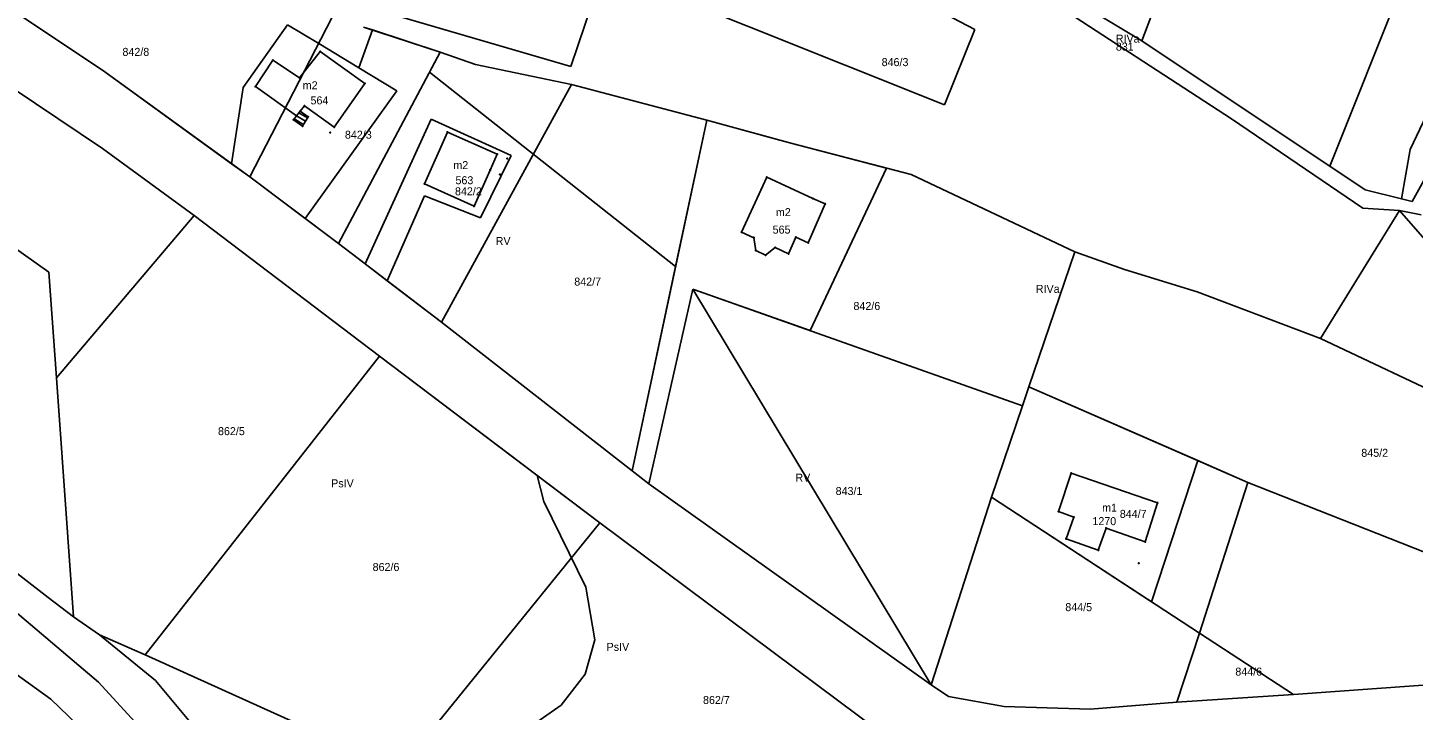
# Model space of a CAD drawing. Extents: x 7498273 to 7499989, y 5499795 to 5500810.
# Drawn here: x 7499281.1 to 7499540.8, y 5500223.1 to 5500351 of the extents above; entities that cross this region are included whole.
import ezdxf

# ---------------------------------------------------------------- set-up
doc = ezdxf.new("R2010")
doc.units = 0
for name, color, linetype in [('209-oznaczenie konturu klasyfikacyjnego', 7, 'Continuous'), ('211-numer działki ewidencyjnej', 7, 'Continuous'), ('217-kontur klasyfikacyjny', 7, 'Continuous'), ('218-kontur użytku gruntowego', 7, 'Continuous'), ('219-działka ewidencyjna', 7, 'Continuous'), ('312-budynek ewidencyjny', 7, 'Continuous'), ('312-oznaczenie budynku ewidencyjnego', 7, 'Continuous'), ('312-oznaczenie budynku ewidencyjnego-Atr117', 7, 'Continuous'), ('352-schody', 7, 'Continuous'), ('Punkt budynku', 7, 'Continuous')]:
    doc.layers.add(name, color=color, linetype=linetype)

# ---------------------------------------------------------------- blocks, each defined once
blk = doc.blocks.new('PUNKTBUD')
blk.add_circle((0, 0), 0.09)

msp = doc.modelspace()

# ---------------------------------------------------------------- linework, layer by layer
at = {"layer": '217-kontur klasyfikacyjny'}
for points in [[(7499458.6, 5500350.63), (7499417.66, 5500372.13)], [(7499259.58, 5500366.67), (7499295.09, 5500343.03)], [(7499208.57, 5500359.47), (7499285.04, 5500305.16)], [(7499397.37, 5500358.71), (7499452.93, 5500336.49)], [(7499489.91, 5500348.52), (7499474.21, 5500358.01)], [(7499525.14, 5500325.03), (7499538.87, 5500359.33)], [(7499506.72, 5500333.87), (7499473.66, 5500355.38)], [(7499295.11, 5500328.33), (7499261.58, 5500350.82)], [(7499321.5, 5500339.77), (7499329.78, 5500351.5)], [(7499329.78, 5500351.5), (7499335.63, 5500347.98)], [(7499343.16, 5500343.43), (7499345.71, 5500350.55)], [(7499345.71, 5500350.55), (7499344.06, 5500351.09)], [(7499358.4, 5500346.36), (7499345.71, 5500350.55)], [(7499452.93, 5500336.49), (7499458.6, 5500350.63)], [(7499335.63, 5500347.98), (7499343.16, 5500343.43)], [(7499525.14, 5500325.03), (7499489.91, 5500348.52)], [(7499356.41, 5500342.63), (7499358.4, 5500346.36)], [(7499295.09, 5500343.03), (7499319.28, 5500325.48)], [(7499343.16, 5500343.43), (7499350.27, 5500339.15)], [(7499402.54, 5500306.22), (7499356.41, 5500342.63)], [(7499319.28, 5500325.48), (7499321.5, 5500339.77)], [(7499350.27, 5500339.15), (7499333.07, 5500315.22)], [(7499551.56, 5500338.06), (7499540.6, 5500318.38)], [(7499344.32, 5500306.71), (7499356.71, 5500333.8)], [(7499356.71, 5500333.8), (7499371.68, 5500327.04)], [(7499402.54, 5500306.22), (7499408.39, 5500333.62)], [(7499408.39, 5500333.62), (7499420.71, 5500330.27)], [(7499531.32, 5500317.16), (7499506.72, 5500333.87)], [(7499420.71, 5500330.27), (7499424.4, 5500329.27)], [(7499424.4, 5500329.27), (7499442.08, 5500324.67)], [(7499312.31, 5500315.76), (7499295.11, 5500328.33)], [(7499371.68, 5500327.04), (7499365.95, 5500315.31)], [(7499442.08, 5500324.67), (7499427.76, 5500294.2)], [(7499531.78, 5500320.61), (7499525.14, 5500325.03)], [(7499355.47, 5500319.45), (7499348.49, 5500303.53)], [(7499365.95, 5500315.31), (7499355.47, 5500319.45)], [(7499538.62, 5500318.88), (7499531.78, 5500320.61)], [(7499540.6, 5500318.38), (7499538.62, 5500318.88)], [(7499538.24, 5500316.71), (7499531.32, 5500317.16)], [(7499533.3, 5500308.74), (7499538.24, 5500316.71)], [(7499542.28, 5500315.9), (7499538.24, 5500316.71)], [(7499286.51, 5500285.37), (7499312.31, 5500315.76)], [(7499347, 5500289.39), (7499312.31, 5500315.76)], [(7499333.07, 5500315.22), (7499339.32, 5500310.52)], [(7499339.32, 5500310.52), (7499344.32, 5500306.71)], [(7499468.74, 5500283.69), (7499477.36, 5500308.96)], [(7499477.36, 5500308.96), (7499486.65, 5500305.68)], [(7499523.41, 5500292.76), (7499533.3, 5500308.74)], [(7499394.37, 5500267.95), (7499402.54, 5500306.22)], [(7499486.65, 5500305.68), (7499500.32, 5500301.49)], [(7499285.04, 5500305.16), (7499286.51, 5500285.37)], [(7499348.49, 5500303.53), (7499358.68, 5500295.76)], [(7499405.78, 5500301.97), (7499397.53, 5500265.51)], [(7499450.45, 5500227.85), (7499405.78, 5500301.97)], [(7499427.76, 5500294.2), (7499405.78, 5500301.97)], [(7499500.32, 5500301.49), (7499523.41, 5500292.76)], [(7499358.68, 5500295.76), (7499394.37, 5500267.95)], [(7499376.59, 5500267.07), (7499347, 5500289.39)], [(7499286.51, 5500285.37), (7499289.68, 5500240.61)], [(7499467.53, 5500280.14), (7499468.74, 5500283.69)], [(7499468.74, 5500283.69), (7499500.43, 5500269.87)], [(7499461.77, 5500263.01), (7499467.53, 5500280.14)], [(7499500.43, 5500269.87), (7499491.75, 5500243.41)], [(7499509.82, 5500265.78), (7499500.43, 5500269.87)], [(7499377.84, 5500262.22), (7499376.59, 5500267.07)], [(7499388.36, 5500258.19), (7499376.59, 5500267.07)], [(7499397.53, 5500265.51), (7499450.45, 5500227.85)], [(7499551.8, 5500249.17), (7499509.82, 5500265.78)], [(7499385.71, 5500246.15), (7499377.84, 5500262.22)], [(7499491.75, 5500243.41), (7499461.77, 5500263.01)], [(7499441, 5500218.92), (7499388.36, 5500258.19)], [(7499387.42, 5500236.27), (7499385.71, 5500246.15)], [(7499289.68, 5500240.61), (7499294.55, 5500237.23)], [(7499294.55, 5500237.23), (7499303.11, 5500233.48)], [(7499385.58, 5500229.81), (7499387.42, 5500236.27)], [(7499303.11, 5500233.48), (7499350.77, 5500211.94)], [(7499381.1, 5500224.01), (7499385.58, 5500229.81)], [(7499450.45, 5500227.85), (7499453.66, 5500225.64)], [(7499518.38, 5500226), (7499571.25, 5500229.86)], [(7499453.66, 5500225.64), (7499464.14, 5500223.76)], [(7499496.51, 5500224.58), (7499518.38, 5500226)], [(7499373.19, 5500218.55), (7499381.1, 5500224.01)], [(7499464.14, 5500223.76), (7499480.25, 5500223.29)], [(7499480.25, 5500223.29), (7499496.51, 5500224.58)]]:
    msp.add_lwpolyline(points, dxfattribs=at)
at = {"layer": '218-kontur użytku gruntowego'}
for points in [[(7499458.6, 5500350.63), (7499417.66, 5500372.13)], [(7499259.58, 5500366.67), (7499295.09, 5500343.03)], [(7499208.57, 5500359.47), (7499285.04, 5500305.16)], [(7499397.37, 5500358.71), (7499452.93, 5500336.49)], [(7499489.91, 5500348.52), (7499474.21, 5500358.01)], [(7499525.14, 5500325.03), (7499538.87, 5500359.33)], [(7499506.72, 5500333.87), (7499473.66, 5500355.38)], [(7499295.11, 5500328.33), (7499261.58, 5500350.82)], [(7499321.5, 5500339.77), (7499329.78, 5500351.5)], [(7499329.78, 5500351.5), (7499335.63, 5500347.98)], [(7499343.16, 5500343.43), (7499345.71, 5500350.55)], [(7499345.71, 5500350.55), (7499344.06, 5500351.09)], [(7499358.4, 5500346.36), (7499345.71, 5500350.55)], [(7499452.93, 5500336.49), (7499458.6, 5500350.63)], [(7499335.63, 5500347.98), (7499343.16, 5500343.43)], [(7499525.14, 5500325.03), (7499489.91, 5500348.52)], [(7499356.41, 5500342.63), (7499358.4, 5500346.36)], [(7499295.09, 5500343.03), (7499319.28, 5500325.48)], [(7499350.27, 5500339.15), (7499343.16, 5500343.43)], [(7499402.54, 5500306.22), (7499356.41, 5500342.63)], [(7499319.28, 5500325.48), (7499321.5, 5500339.77)], [(7499333.07, 5500315.22), (7499350.27, 5500339.15)], [(7499551.56, 5500338.06), (7499540.6, 5500318.38)], [(7499344.32, 5500306.71), (7499356.71, 5500333.8)], [(7499356.71, 5500333.8), (7499371.68, 5500327.04)], [(7499408.39, 5500333.62), (7499402.54, 5500306.22)], [(7499420.71, 5500330.27), (7499408.39, 5500333.62)], [(7499531.32, 5500317.16), (7499506.72, 5500333.87)], [(7499424.4, 5500329.27), (7499420.71, 5500330.27)], [(7499442.08, 5500324.67), (7499424.4, 5500329.27)], [(7499312.31, 5500315.76), (7499295.11, 5500328.33)], [(7499371.68, 5500327.04), (7499365.95, 5500315.31)], [(7499319.28, 5500325.48), (7499322.7, 5500323)], [(7499427.76, 5500294.2), (7499442.08, 5500324.67)], [(7499531.78, 5500320.61), (7499525.14, 5500325.03)], [(7499322.7, 5500323), (7499333.07, 5500315.22)], [(7499355.47, 5500319.45), (7499348.49, 5500303.53)], [(7499365.95, 5500315.31), (7499355.47, 5500319.45)], [(7499538.62, 5500318.88), (7499531.78, 5500320.61)], [(7499540.6, 5500318.38), (7499538.62, 5500318.88)], [(7499538.24, 5500316.71), (7499531.32, 5500317.16)], [(7499533.3, 5500308.74), (7499538.24, 5500316.71)], [(7499542.28, 5500315.9), (7499538.24, 5500316.71)], [(7499312.31, 5500315.76), (7499286.51, 5500285.37)], [(7499347, 5500289.39), (7499312.31, 5500315.76)], [(7499333.07, 5500315.22), (7499339.32, 5500310.52)], [(7499339.32, 5500310.52), (7499344.32, 5500306.71)], [(7499468.74, 5500283.69), (7499477.36, 5500308.96)], [(7499477.36, 5500308.96), (7499486.65, 5500305.68)], [(7499523.41, 5500292.76), (7499533.3, 5500308.74)], [(7499344.32, 5500306.71), (7499348.49, 5500303.53)], [(7499394.37, 5500267.95), (7499402.54, 5500306.22)], [(7499486.65, 5500305.68), (7499500.32, 5500301.49)], [(7499285.04, 5500305.16), (7499286.51, 5500285.37)], [(7499348.49, 5500303.53), (7499358.68, 5500295.76)], [(7499397.53, 5500265.51), (7499405.78, 5500301.97)], [(7499405.78, 5500301.97), (7499427.76, 5500294.2)], [(7499450.45, 5500227.85), (7499405.78, 5500301.97)], [(7499500.32, 5500301.49), (7499523.41, 5500292.76)], [(7499358.68, 5500295.76), (7499394.37, 5500267.95)], [(7499376.59, 5500267.07), (7499347, 5500289.39)], [(7499286.51, 5500285.37), (7499289.68, 5500240.61)], [(7499468.74, 5500283.69), (7499467.53, 5500280.14)], [(7499500.43, 5500269.87), (7499468.74, 5500283.69)], [(7499467.53, 5500280.14), (7499461.77, 5500263.01)], [(7499491.75, 5500243.41), (7499500.43, 5500269.87)], [(7499509.82, 5500265.78), (7499500.43, 5500269.87)], [(7499377.84, 5500262.22), (7499376.59, 5500267.07)], [(7499388.36, 5500258.19), (7499376.59, 5500267.07)], [(7499394.37, 5500267.95), (7499397.53, 5500265.51)], [(7499397.53, 5500265.51), (7499450.45, 5500227.85)], [(7499551.8, 5500249.17), (7499509.82, 5500265.78)], [(7499385.71, 5500246.15), (7499377.84, 5500262.22)], [(7499461.77, 5500263.01), (7499491.75, 5500243.41)], [(7499441, 5500218.92), (7499388.36, 5500258.19)], [(7499387.42, 5500236.27), (7499385.71, 5500246.15)], [(7499294.34, 5500228.32), (7499275.8, 5500243.99)], [(7499289.68, 5500240.61), (7499294.55, 5500237.23)], [(7499294.55, 5500237.23), (7499303.11, 5500233.48)], [(7499385.58, 5500229.81), (7499387.42, 5500236.27)], [(7499285.41, 5500225.16), (7499274.61, 5500232.89)], [(7499303.11, 5500233.48), (7499350.77, 5500211.94)], [(7499324.4, 5500195.55), (7499294.34, 5500228.32)], [(7499381.1, 5500224.01), (7499385.58, 5500229.81)], [(7499450.45, 5500227.85), (7499453.66, 5500225.64)], [(7499518.38, 5500226), (7499571.25, 5500229.86)], [(7499301.97, 5500209.24), (7499285.41, 5500225.16)], [(7499453.66, 5500225.64), (7499464.14, 5500223.76)], [(7499496.51, 5500224.58), (7499518.38, 5500226)], [(7499373.19, 5500218.55), (7499381.1, 5500224.01)], [(7499464.14, 5500223.76), (7499480.25, 5500223.29)], [(7499480.25, 5500223.29), (7499496.51, 5500224.58)]]:
    msp.add_lwpolyline(points, dxfattribs=at)
at = {"layer": '219-działka ewidencyjna'}
for points in [[(7499382.89, 5500343.71), (7499400.41, 5500395.43)], [(7499489.91, 5500348.52), (7499500.4, 5500376.17)], [(7499295.09, 5500343.03), (7499259.58, 5500366.67)], [(7499285.04, 5500305.16), (7499208.57, 5500359.47)], [(7499474.21, 5500358.01), (7499489.91, 5500348.52)], [(7499473.66, 5500355.38), (7499506.72, 5500333.87)], [(7499322.7, 5500323), (7499338.12, 5500352.79)], [(7499345.42, 5500354.59), (7499382.89, 5500343.71)], [(7499261.58, 5500350.82), (7499295.11, 5500328.33)], [(7499344.06, 5500351.09), (7499358.4, 5500346.36)], [(7499531.78, 5500320.61), (7499489.91, 5500348.52)], [(7499339.32, 5500310.52), (7499358.4, 5500346.36)], [(7499358.4, 5500346.36), (7499365.03, 5500344.04)], [(7499295.09, 5500343.03), (7499322.7, 5500323)], [(7499383.04, 5500340.33), (7499365.03, 5500344.04)], [(7499358.68, 5500295.76), (7499383.04, 5500340.33)], [(7499383.04, 5500340.33), (7499408.39, 5500333.62)], [(7499540.23, 5500328.12), (7499546.3, 5500340.91)], [(7499540.6, 5500318.38), (7499551.56, 5500338.06)], [(7499394.37, 5500267.95), (7499408.39, 5500333.62)], [(7499408.39, 5500333.62), (7499424.4, 5500329.27)], [(7499506.72, 5500333.87), (7499531.32, 5500317.16)], [(7499424.4, 5500329.27), (7499446.67, 5500323.48)], [(7499295.11, 5500328.33), (7499312.31, 5500315.76)], [(7499538.62, 5500318.88), (7499540.23, 5500328.12)], [(7499322.7, 5500323), (7499339.32, 5500310.52)], [(7499446.67, 5500323.48), (7499477.36, 5500308.96)], [(7499531.78, 5500320.61), (7499538.62, 5500318.88)], [(7499538.62, 5500318.88), (7499540.6, 5500318.38)], [(7499538.24, 5500316.71), (7499523.41, 5500292.76)], [(7499531.32, 5500317.16), (7499538.24, 5500316.71)], [(7499538.24, 5500316.71), (7499564.26, 5500286.9)], [(7499538.24, 5500316.71), (7499542.28, 5500315.9)], [(7499286.51, 5500285.37), (7499312.31, 5500315.76)], [(7499312.31, 5500315.76), (7499347, 5500289.39)], [(7499358.68, 5500295.76), (7499339.32, 5500310.52)], [(7499477.36, 5500308.96), (7499468.74, 5500283.69)], [(7499477.36, 5500308.96), (7499486.65, 5500305.68)], [(7499486.65, 5500305.68), (7499500.32, 5500301.49)], [(7499285.04, 5500305.16), (7499286.51, 5500285.37)], [(7499397.53, 5500265.51), (7499405.78, 5500301.97)], [(7499405.78, 5500301.97), (7499467.53, 5500280.14)], [(7499500.32, 5500301.49), (7499523.41, 5500292.76)], [(7499358.68, 5500295.76), (7499394.37, 5500267.95)], [(7499575.27, 5500268.23), (7499523.41, 5500292.76)], [(7499303.11, 5500233.48), (7499347, 5500289.39)], [(7499347, 5500289.39), (7499388.36, 5500258.19)], [(7499286.51, 5500285.37), (7499289.68, 5500240.61)], [(7499467.53, 5500280.14), (7499468.74, 5500283.69)], [(7499468.74, 5500283.69), (7499509.82, 5500265.78)], [(7499461.77, 5500263.01), (7499467.53, 5500280.14)], [(7499394.37, 5500267.95), (7499397.53, 5500265.51)], [(7499397.53, 5500265.51), (7499450.45, 5500227.85)], [(7499500.71, 5500237.55), (7499509.82, 5500265.78)], [(7499509.82, 5500265.78), (7499551.8, 5500249.17)], [(7499450.45, 5500227.85), (7499461.77, 5500263.01)], [(7499461.77, 5500263.01), (7499500.71, 5500237.55)], [(7499350.77, 5500211.94), (7499388.36, 5500258.19)], [(7499441, 5500218.92), (7499388.36, 5500258.19)], [(7499275.99, 5500251.14), (7499284.91, 5500244.23)], [(7499284.91, 5500244.23), (7499289.68, 5500240.61)], [(7499289.68, 5500240.61), (7499294.55, 5500237.23)], [(7499294.55, 5500237.23), (7499305.06, 5500228.64)], [(7499294.55, 5500237.23), (7499303.11, 5500233.48)], [(7499496.51, 5500224.58), (7499500.71, 5500237.55)], [(7499500.71, 5500237.55), (7499518.38, 5500226)], [(7499303.11, 5500233.48), (7499350.77, 5500211.94)], [(7499305.06, 5500228.64), (7499322.55, 5500207.66)], [(7499450.45, 5500227.85), (7499453.66, 5500225.64)], [(7499518.38, 5500226), (7499571.25, 5500229.86)], [(7499453.66, 5500225.64), (7499464.14, 5500223.76)], [(7499496.51, 5500224.58), (7499518.38, 5500226)], [(7499464.14, 5500223.76), (7499480.25, 5500223.29)], [(7499480.25, 5500223.29), (7499496.51, 5500224.58)]]:
    msp.add_lwpolyline(points, dxfattribs=at)
at = {"layer": '312-budynek ewidencyjny'}
for points in [[(7499323.78, 5500339.93), (7499327.06, 5500344.87)], [(7499327.06, 5500344.87), (7499332.06, 5500341.55)], [(7499332.06, 5500341.55), (7499335.91, 5500346.48)], [(7499335.91, 5500346.48), (7499344.31, 5500340.53)], [(7499331.48, 5500334.46), (7499323.78, 5500339.93)], [(7499344.31, 5500340.53), (7499338.54, 5500332.35)], [(7499332.18, 5500335.32), (7499331.48, 5500334.46)], [(7499332.96, 5500336.29), (7499332.18, 5500335.32)], [(7499338.54, 5500332.35), (7499332.96, 5500336.29)], [(7499355.49, 5500321.69), (7499359.77, 5500331.4)], [(7499359.77, 5500331.4), (7499369.08, 5500327.28)], [(7499369.08, 5500327.28), (7499367.76, 5500324.28)], [(7499367.76, 5500324.28), (7499364.77, 5500317.52)], [(7499364.77, 5500317.52), (7499355.49, 5500321.69)], [(7499414.9, 5500312.66), (7499419.62, 5500322.93)], [(7499419.62, 5500322.93), (7499428.24, 5500318.97)], [(7499428.24, 5500318.97), (7499430.58, 5500317.95)], [(7499430.58, 5500317.95), (7499427.41, 5500310.67)], [(7499417.17, 5500311.62), (7499414.9, 5500312.66)], [(7499417.56, 5500309.24), (7499417.17, 5500311.62)], [(7499425.07, 5500311.69), (7499423.71, 5500308.61)], [(7499427.41, 5500310.67), (7499425.07, 5500311.69)], [(7499419.4, 5500308.36), (7499417.56, 5500309.24)], [(7499421.21, 5500309.76), (7499419.4, 5500308.36)], [(7499423.71, 5500308.61), (7499421.21, 5500309.76)], [(7499474.32, 5500260.29), (7499476.7, 5500267.48)], [(7499476.7, 5500267.48), (7499492.89, 5500261.94)], [(7499492.89, 5500261.94), (7499490.57, 5500254.62)], [(7499477.15, 5500259.28), (7499474.32, 5500260.29)], [(7499475.74, 5500255.22), (7499477.15, 5500259.28)], [(7499483.21, 5500257.2), (7499481.77, 5500253.1)], [(7499490.57, 5500254.62), (7499483.21, 5500257.2)], [(7499481.77, 5500253.1), (7499475.74, 5500255.22)]]:
    msp.add_lwpolyline(points, dxfattribs=at)
at = {"layer": '352-schody'}
msp.add_lwpolyline([(7499330.93, 5500333.72), (7499331.48, 5500334.46), (7499332.18, 5500335.32), (7499333.64, 5500334.28), (7499332.62, 5500332.54)], close=True, dxfattribs=at)
msp.add_lwpolyline([(7499330.93, 5500333.72), (7499331.48, 5500334.46), (7499332.18, 5500335.32), (7499333.64, 5500334.28), (7499332.62, 5500332.54)], close=True, dxfattribs=at)
for points in [[(7499333.151, 5500333.446), (7499331.462, 5500334.436)], [(7499333.505, 5500334.05), (7499331.908, 5500334.986)], [(7499332.797, 5500332.842), (7499331.042, 5500333.871)]]:
    msp.add_lwpolyline(points, dxfattribs=at)

# ---------------------------------------------------------------- block references
at = {"layer": 'Punkt budynku'}
for p in [(7499327.06, 5500344.87), (7499335.91, 5500346.48), (7499323.78, 5500339.93), (7499332.06, 5500341.55), (7499344.31, 5500340.53), (7499331.48, 5500334.46), (7499332.18, 5500335.32), (7499332.96, 5500336.29), (7499333.64, 5500334.28), (7499330.93, 5500333.72), (7499332.62, 5500332.54), (7499338.54, 5500332.35), (7499359.77, 5500331.4), (7499337.81, 5500331.32), (7499369.08, 5500327.28), (7499370.97, 5500326.45), (7499367.76, 5500324.28), (7499355.49, 5500321.69), (7499369.6, 5500323.46), (7499419.62, 5500322.93), (7499428.24, 5500318.97), (7499364.77, 5500317.52), (7499430.58, 5500317.95), (7499414.9, 5500312.66), (7499417.17, 5500311.62), (7499425.07, 5500311.69), (7499427.41, 5500310.67), (7499417.56, 5500309.24), (7499419.4, 5500308.36), (7499421.21, 5500309.76), (7499423.71, 5500308.61), (7499476.7, 5500267.48), (7499492.89, 5500261.94), (7499474.32, 5500260.29), (7499477.15, 5500259.28), (7499483.21, 5500257.2), (7499475.74, 5500255.22), (7499490.57, 5500254.62), (7499481.77, 5500253.1), (7499489.34, 5500250.63)]:
    msp.add_blockref('PUNKTBUD', p, dxfattribs=at)

# ---------------------------------------------------------------- texts
at = {"layer": '209-oznaczenie konturu klasyfikacyjnego'}
for s, p in [('RIVa', (7499485.05, 5500348.16)), ('RV', (7499368.81, 5500310.25)), ('RIVa', (7499470.06, 5500301.28)), ('RV', (7499424.99, 5500265.91)), ('PsIV', (7499337.97, 5500264.85)), ('PsIV', (7499389.6, 5500234.21))]:
    msp.add_text(s, height=1.5, dxfattribs=at).set_placement(p)
at = {"layer": '211-numer działki ewidencyjnej'}
for s, p in [('842/8', (7499298.85, 5500345.68)), ('831', (7499485.05, 5500346.66)), ('846/3', (7499441.15, 5500343.76)), ('842/3', (7499340.55, 5500330.16)), ('842/2', (7499361.18, 5500319.56)), ('842/7', (7499383.54, 5500302.64)), ('842/6', (7499435.87, 5500298.07)), ('862/5', (7499316.76, 5500274.62)), ('845/2', (7499531.06, 5500270.56)), ('843/1', (7499432.53, 5500263.41)), ('844/7', (7499485.8, 5500259.12)), ('862/6', (7499345.74, 5500249.17)), ('844/5', (7499475.58, 5500241.65)), ('844/6', (7499507.45, 5500229.57)), ('862/7', (7499407.67, 5500224.25))]:
    msp.add_text(s, height=1.5, dxfattribs=at).set_placement(p)
at = {"layer": '312-oznaczenie budynku ewidencyjnego'}
for s, p in [('564', (7499334.1, 5500336.59)), ('563', (7499361.27, 5500321.63)), ('565', (7499420.72, 5500312.38)), ('1270', (7499480.66, 5500257.76))]:
    msp.add_text(s, height=1.5, dxfattribs=at).set_placement(p)
at = {"layer": '312-oznaczenie budynku ewidencyjnego-Atr117'}
for s, p in [('m2', (7499332.636, 5500339.42)), ('m2', (7499360.876, 5500324.46)), ('m2', (7499421.326, 5500315.65)), ('m1', (7499482.485, 5500260.29))]:
    msp.add_text(s, height=1.5, dxfattribs=at).set_placement(p)

doc.saveas('drawing.dxf')
